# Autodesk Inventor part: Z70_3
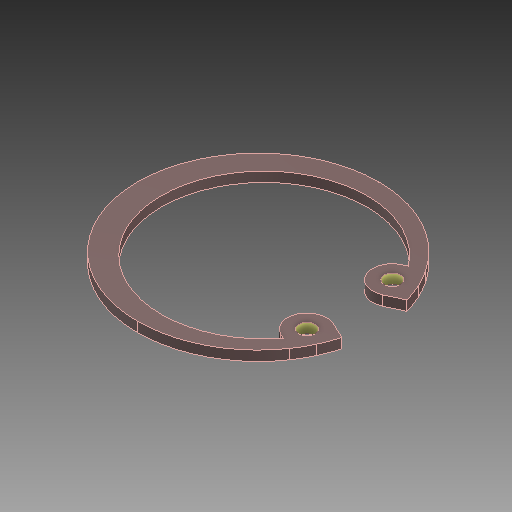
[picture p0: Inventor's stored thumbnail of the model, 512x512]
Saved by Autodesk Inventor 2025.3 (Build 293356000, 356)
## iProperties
Created: 2025-03
Part Number: Z70_3
Material: Všeobecné
Document SubType Name: Modeling
Designer: Patrik
Density: 1 g/cm^3
Appearance: Výchozí
Mass: 0.233745 g
Surface Area: 6.05444 cm^2
Volume: 0.233745 cm^3
Author: Patrik
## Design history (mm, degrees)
feature "Base1"
node "Těleso1"
